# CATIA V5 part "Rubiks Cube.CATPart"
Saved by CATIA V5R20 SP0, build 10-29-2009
Part number: Rubiks Cube
Source: Unknown
Bounding box of the stored display mesh (mm): x 0 to 55.8, y 18.6 to 74.4, z 32.002 to 87.802
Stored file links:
  C:\Users\Ikarus\OneDrive - FH JOANNEUM\BAC - Arbeit 1\CAD Modell\CAD-Modell-Step files\Cube\Rubiks Cube.CATPart
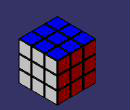
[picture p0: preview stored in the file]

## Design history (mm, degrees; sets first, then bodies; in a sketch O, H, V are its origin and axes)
Body1 "Cube.1\\Hauptkörper" (main body)
  Solid1: solid without history
Body2 "Cube.2\\Hauptkörper"
  Solid2: solid without history
Body3 "Cube.3\\Hauptkörper"
  Solid3: solid without history
Body4 "Cube.4\\Hauptkörper"
  Solid4: solid without history
Body5 "Cube.5\\Hauptkörper"
  Solid5: solid without history
Body6 "Cube.6\\Hauptkörper"
  Solid6: solid without history
Body7 "Cube.7\\Hauptkörper"
  Solid7: solid without history
Body8 "Cube.8\\Hauptkörper"
  Solid8: solid without history
Body9 "Cube.9\\Hauptkörper"
  Solid9: solid without history
Body10 "Cube.10\\Hauptkörper"
  Solid10: solid without history
Body11 "Cube.11\\Hauptkörper"
  Solid11: solid without history
Body12 "Cube.12\\Hauptkörper"
  Solid12: solid without history
Body13 "Cube.13\\Hauptkörper"
  Solid13: solid without history
Body14 "Cube.14\\Hauptkörper"
  Solid14: solid without history
Body15 "Cube.15\\Hauptkörper"
  Solid15: solid without history
Body16 "Cube.16\\Hauptkörper"
  Solid16: solid without history
Body17 "Cube.17\\Hauptkörper"
  Solid17: solid without history
Body18 "Cube.18\\Hauptkörper"
  Solid18: solid without history
Body19 "Cube.19\\Hauptkörper"
  Solid19: solid without history
Body20 "Cube.20\\Hauptkörper"
  Solid20: solid without history
Body21 "Cube.21\\Hauptkörper"
  Solid21: solid without history
Body22 "Cube.22\\Hauptkörper"
  Solid22: solid without history
Body23 "Cube.23\\Hauptkörper"
  Solid23: solid without history
Body24 "Cube.24\\Hauptkörper"
  Solid24: solid without history
Body25 "Cube.25\\Hauptkörper"
  Solid25: solid without history
Body26 "Cube.26\\Hauptkörper"
  Solid26: solid without history
Body27 "Cube.27\\Hauptkörper"
  Solid27: solid without history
